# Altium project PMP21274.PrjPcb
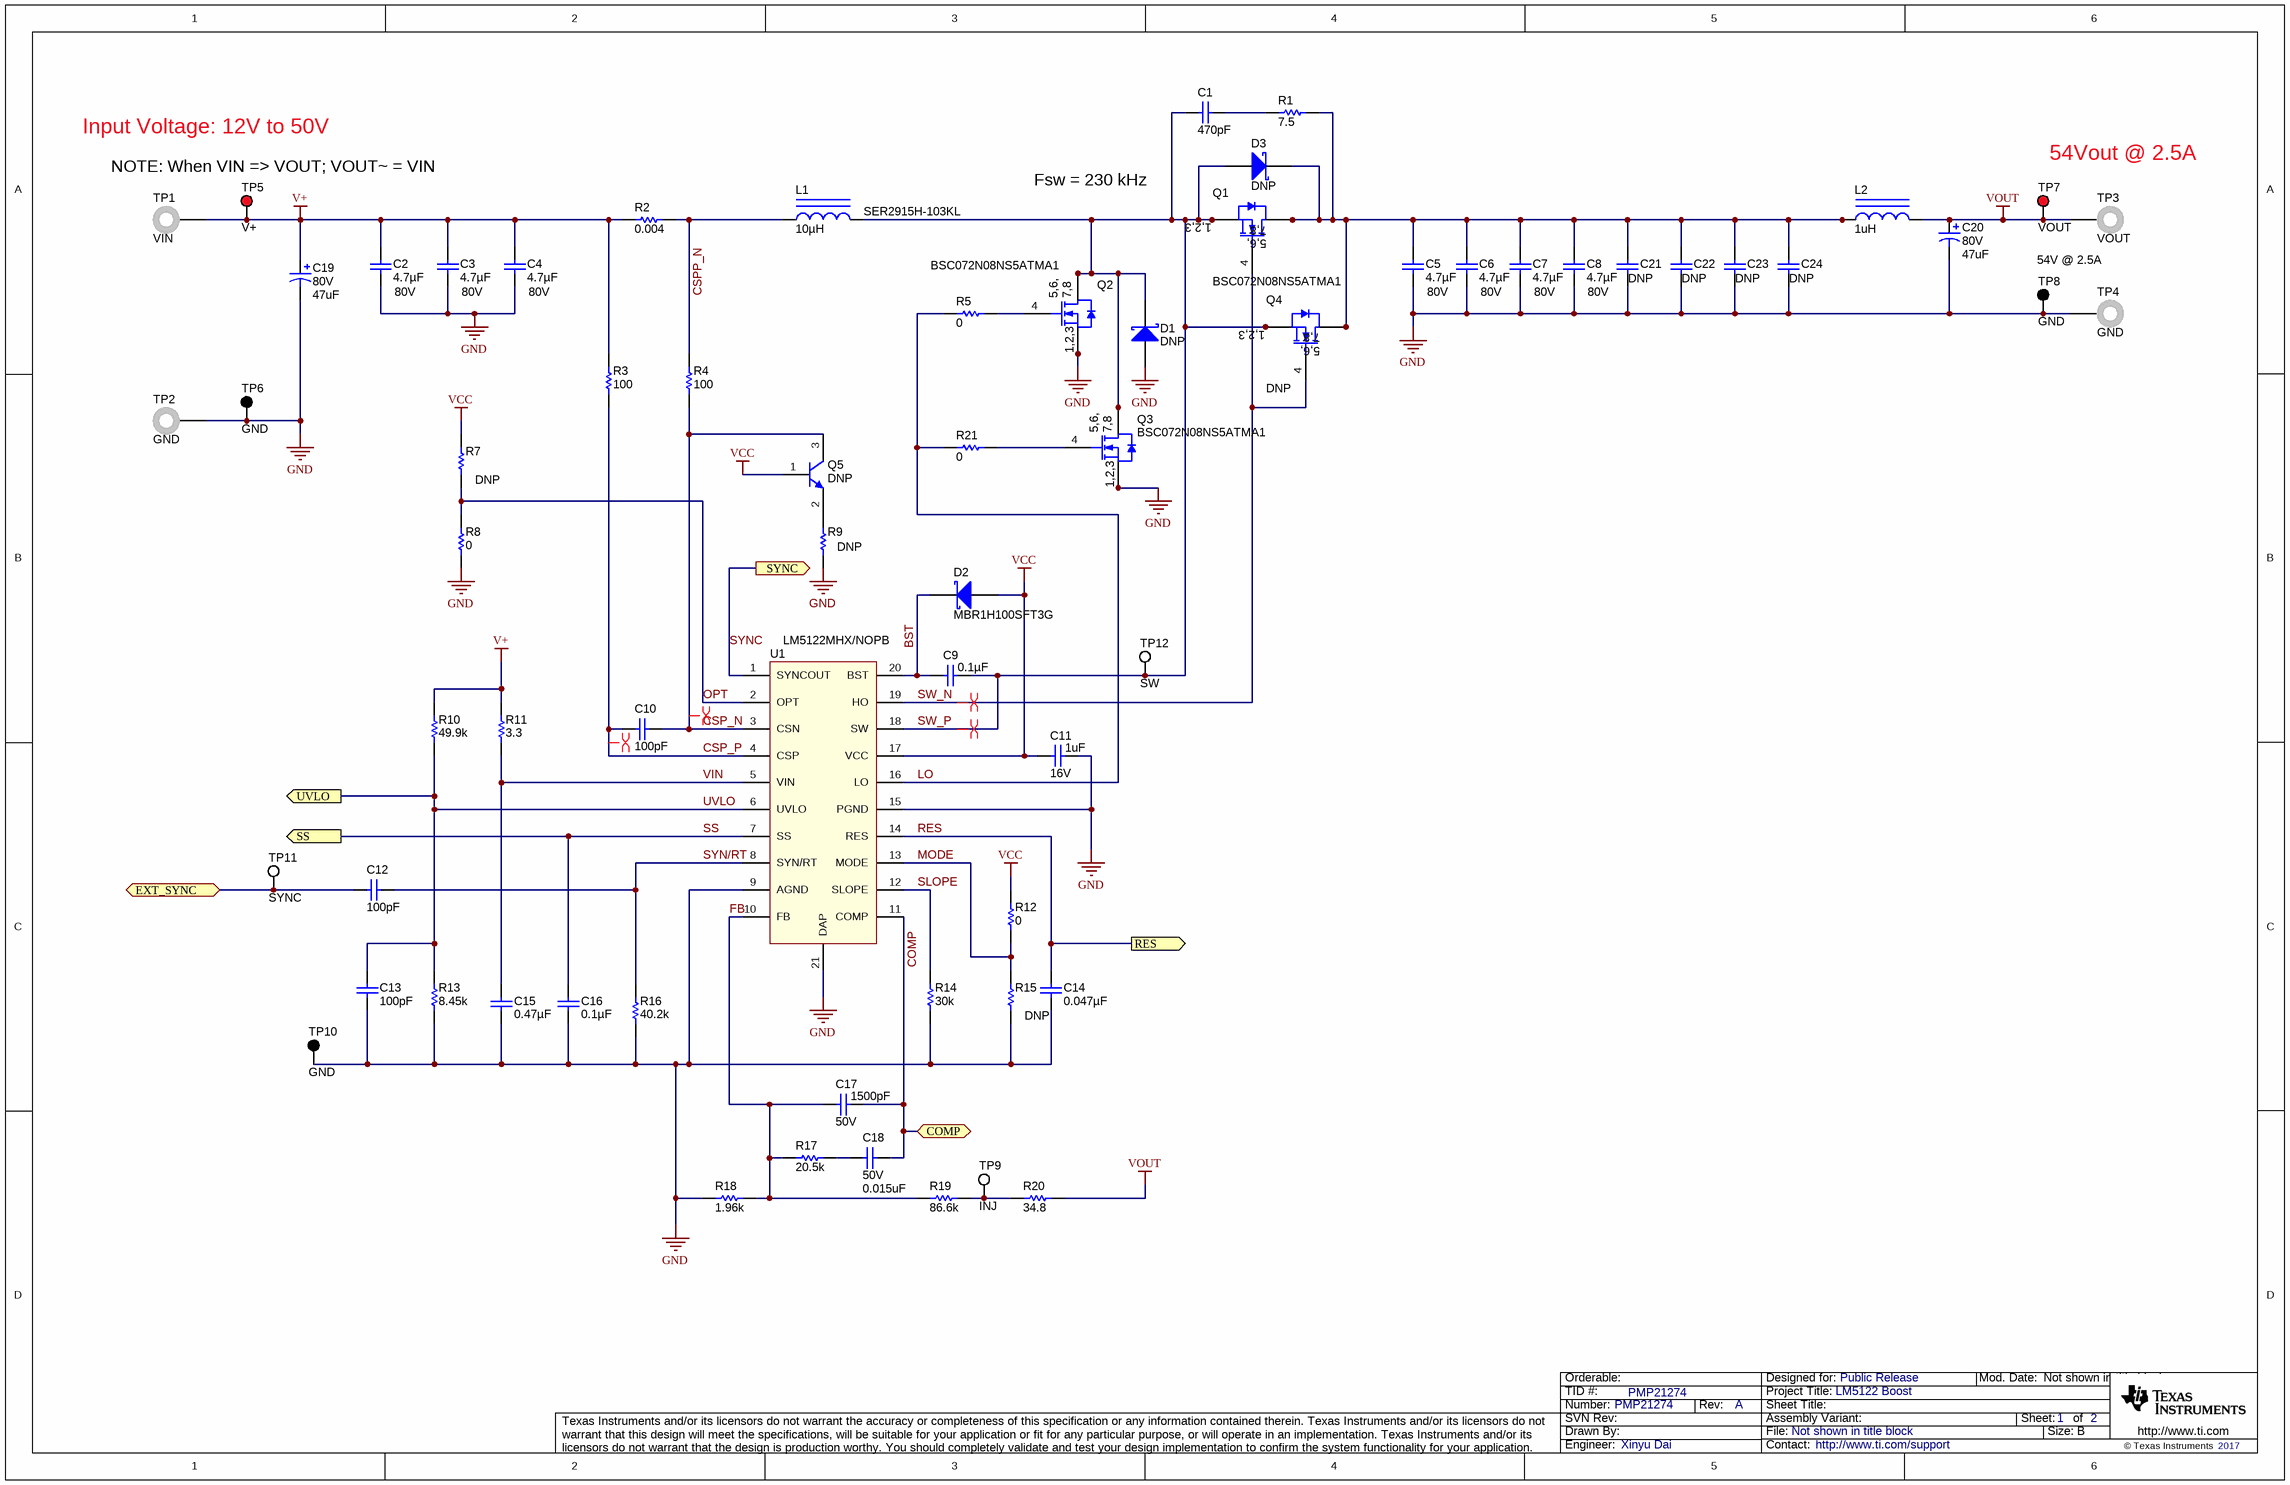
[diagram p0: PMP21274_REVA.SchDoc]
CopyrightYear: 2017; PCB_Layout: Xinyu Dai; PCB_Rev: A; PRJ_Customer: Public Release; PRJ_Engineer: Xinyu Dai; PRJ_Number: PMP21274; PRJ_Title: LM5122 Boost; SCH_Rev: A; TechSupport: http://www.ti.com/support; TID: PMP21274
2 sheets, 83 parts. Net scope: flat (ports and power ports of the same name join across sheets).
Board file: PMP21274_REVA.PcbDoc
Sheets:
  PMP21274_REVA.SchDoc
  PMP21274_REVA_Hardware.SchDoc

## Sheet PMP21274_REVA.SchDoc
size 431 x 279 mm; Date: Not shown in title block; ApprovedBy: Not shown in title block; CheckedBy: Not shown in title block; Author: Not shown in title block; CompanyName: Not shown in title block; Engineer: Not shown in title block; Organization: Not shown in title block; Address1: Not shown in title block; Address2: Not shown in title block; Address3: Not shown in title block; Address4: Not shown in title block; DocumentNumber: 1; Revision: Use project parameter SCH_Rev; SheetNumber: 1; SheetTotal: 2; PageSetup: Record=PageOptions¦CenterHorizontal=True¦CenterVertical=True¦PrintScale=1.00¦XCorrection=1.00¦YCorrection=1.00¦PrintKind=0¦BorderSize=5000000¦LeftOffset=0¦BottomOffset=0¦Orientation=2¦PaperLength=1000¦PaperWidth=1000¦Scale=100¦PaperSource=15¦PrintQuality=600¦MediaType=1¦DitherType=10¦PaperKind=Letter¦PrintScaleMode=1

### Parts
C1  ValueDisplayed: 470pF  [0805L]  (hidden comment: GRM2165C2A471JA01D)
C2  ValueDisplayed: 4.7µF  Value2: 80V  [1210L]  (hidden comment: GRM32ER71K475KE14L)
C3  ValueDisplayed: 4.7µF  Value2: 80V  [1210L]  (hidden comment: GRM32ER71K475KE14L)
C4  ValueDisplayed: 4.7µF  Value2: 80V  [1210L]  (hidden comment: GRM32ER71K475KE14L)
C5  ValueDisplayed: 4.7µF  Value2: 80V  [1210L]  (hidden comment: GRM32ER71K475KE14L)
C6  ValueDisplayed: 4.7µF  Value2: 80V  [1210L]  (hidden comment: GRM32ER71K475KE14L)
C7  ValueDisplayed: 4.7µF  Value2: 80V  [1210L]  (hidden comment: GRM32ER71K475KE14L)
C8  ValueDisplayed: 4.7µF  Value2: 80V  [1210L]  (hidden comment: GRM32ER71K475KE14L)
C9  ValueDisplayed: 0.1µF  [0603L]  (hidden comment: GRM188R71E104KA01D)
C10  ValueDisplayed: 100pF  [0603L]  (hidden comment: GRM1885C1H101JA01D)
C11  VDC_V: 16V  ValueDisplayed: 1uF  [0603L]  (hidden comment: GCM188R71C105KA64D)
C12  ValueDisplayed: 100pF  [0603L]  (hidden comment: GRM1885C1H101JA01D)
C13  ValueDisplayed: 100pF  [0603L]  (hidden comment: GRM1885C1H101JA01D)
C14  ValueDisplayed: 0.047µF  [0603L]  (hidden comment: GRM188R71E473KA01D)
C15  ValueDisplayed: 0.47µF  [0805L]  (hidden comment: GRM21BR72A474KA73L)
C16  ValueDisplayed: 0.1µF  [0603L]  (hidden comment: GRM188R71E104KA01D)
C17  VDC_V: 50V  ValueDisplayed: 1500pF  [0603L]  (hidden comment: GRM1885C1H152JA01D)
C18  VDC_V: 50V  ValueDisplayed: 0.015uF  [0603L]  (hidden comment: GRM188R71H153KA01D)
C19  VDC_V: 80V  ValueDisplayed: 47uF  [SM_RADIAL_G]  (hidden comment: EEE-FK1K470P)
C20  VDC_V: 80V  ValueDisplayed: 47uF  [SM_RADIAL_G]  (hidden comment: EEE-FK1K470P)
C21  DNP  [1210L]
C22  DNP  [1210L]
C23  DNP  [1210L]
C24  DNP  [1210L]
D1  DNP  [SMA]
D2  MBR1H100SFT3G  [SOD-123FL]
D3  DNP  [SMA]
L1  SER2915H-103KL  ValueDisplayed: 10µH  [SER2915H]
L2  ValueDisplayed: 1uH  [XAL4020]  (hidden comment: XAL4020-102MEB)
Q1  BSC072N08NS5ATMA1  [PG-TDSON-8]
Q2  BSC072N08NS5ATMA1  [PG-TDSON-8]
Q3  BSC072N08NS5ATMA1  [PG-TDSON-8]
Q4  DNP  [PG-TDSON-8]
Q5  DNP  [SOT-23L]
R1  ValueDisplayed: 7.5  [2010L]  (hidden comment: ERJ-12ZYJ7R5U)
R2  ValueDisplayed: 0.004  [2512L]  (hidden comment: ERJ-M1WSF4M0U)
R3  ValueDisplayed: 100  [0603L]  (hidden comment: ESR03EZPJ101)
R4  ValueDisplayed: 100  [0603L]  (hidden comment: ESR03EZPJ101)
R5  value 0  [0603L]  (hidden comment: ERJ-3GEY0R00V)
R7  DNP  [0603L]
R8  value 0  [0603L]  (hidden comment: ERJ-3GEY0R00V)
R9  DNP  [0603L]
R10  value 49.9k  [0603L]  (hidden comment: CRCW060349K9FKEA)
R11  value 3.3  [0603L]  (hidden comment: CRCW06033R30JNEA)
R12  value 0  [0603L]  (hidden comment: ERJ-3GEY0R00V)
R13  ValueDisplayed: 8.45k  [0603L]  (hidden comment: CRCW06038K45FKEA)
R14  ValueDisplayed: 30k  [0603L]  (hidden comment: CRCW060330K0JNEA)
R15  DNP  [0603L]
R16  value 40.2k  [0603L]  (hidden comment: CRCW060340K2FKEA)
R17  ValueDisplayed: 20.5k  [0603L]  (hidden comment: CRCW060320K5FKEA)
R18  value 1.96k  [0603L]  (hidden comment: CRCW06031K96FKEA)
R19  ValueDisplayed: 86.6k  [0603L]  (hidden comment: CRCW060386K6FKEA)
R20  ValueDisplayed: 34.8  [0603L]  (hidden comment: CRCW060334R8FKEA)
R21  value 0  [0603L]  (hidden comment: ERJ-3GEY0R00V)
TP1  VIN  [Keystone575-8]
TP2  GND  [Keystone575-8]
TP3  VOUT  [Keystone575-8]
TP4  GND  [Keystone575-8]
TP5  V+  [Keystone5010]
TP6  GND  [Keystone5011]
TP7  VOUT  [Keystone5010]
TP8  GND  [Keystone5011]
TP9  INJ  [Keystone5002]
TP10  GND  [Keystone5011]
TP11  SYNC  [Keystone5002]
TP12  SW  [Keystone5002]
U1  LM5122MHX/NOPB  [MXA20A_L]

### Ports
COMP, EXT_SYNC, RES, SS, SYNC (out), UVLO

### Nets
GND: C2.2 C3.2 C4.2 C5.2 C6.2 C7.2 C8.2 C11.1 C13.2 C14.2 C15.2 C16.2 C19.2(-) C20.2(-) C21.2 C22.2 C23.2 C24.2 D1.2(A) Q2.1(S) Q2.2(S) Q2.3(S) Q3.1(S) Q3.2(S) Q3.3(S) R8.1 R9.1 R13.1 R14.1 R15.1 R16.1 R18.1 TP2.1 TP4.1 TP6.1 TP8.1 TP10.1 U1.9(AGND) U1.15(PGND) U1.21(DAP)
V+: C2.1 C3.1 C4.1 C19.1(+) R2.1 R3.2 R10.2 R11.2 TP1.1 TP5.1
VCC: C11.2 D2.2(A) Q5.1(B) R7.2 R12.2 U1.17(VCC)
VOUT: C20.1(+) L2.2 R20.2 TP3.1 TP7.1
BST: C9.2 D2.1(K) U1.20(BST)
COMP: C17.1 C18.1 U1.11(COMP) ; port COMP
CSP_N: C10.1 Q5.3(C) R4.1 U1.3(CSN)
CSP_P: C10.2 R3.1 U1.4(CSP)
CSPP_N: L1.1 R2.2 R4.2
EXT_SYNC: C12.2 TP11.1 ; port EXT_SYNC
FB: C17.2 R17.1 R18.2 R19.1 U1.10(FB)
LO: R5.2 R21.2 U1.16(LO)
MODE: R12.1 R15.2 U1.13(MODE)
OPT: R7.1 R8.2 U1.2(OPT)
RES: C14.1 U1.14(RES) ; port RES
SLOPE: R14.2 U1.12(SLOPE)
SS: C16.1 U1.7(SS) ; port SS
SW_N: Q1.4(G) Q4.4(G) U1.19(HO)
SW_P: C1.2 C9.1 D1.1(K) D3.2(A) L1.2 Q1.1(S) Q1.2(S) Q1.3(S) Q2.5(D) Q2.6(D) Q2.7(D) Q2.8(D) Q2.9(D) Q3.5(D) Q3.6(D) Q3.7(D) Q3.8(D) Q3.9(D) Q4.1(S) Q4.2(S) Q4.3(S) TP12.1 U1.18(SW)
SYN/RT: C12.1 R16.2 U1.8(SYN/RT)
SYNC: U1.1(SYNCOUT) ; port SYNC
UVLO: C13.1 R10.1 R13.2 U1.6(UVLO) ; port UVLO
VIN: C15.1 R11.1 U1.5(VIN)
NetC1_1: C1.1 R1.1
NetC5_1: C5.1 C6.1 C7.1 C8.1 C21.1 C22.1 C23.1 C24.1 D3.1(K) L2.1 Q1.5(D) Q1.6(D) Q1.7(D) Q1.8(D) Q1.9(D) Q4.5(D) Q4.6(D) Q4.7(D) Q4.8(D) Q4.9(D) R1.2
NetC18_2: C18.2 R17.2
NetQ2_4: Q2.4(G) R5.1
NetQ3_4: Q3.4(G) R21.1
NetQ5_2: Q5.2(E) R9.2
NetR19_2: R19.2 R20.1 TP9.1

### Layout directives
differential pair: CSP_N, CSP_P, SW_N, SW_P

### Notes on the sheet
- Input Voltage: 12V to 50V
- NOTE: When VIN => VOUT; VOUT~ = VIN
- 54Vout @ 2.5A
- Fsw = 230 kHz
- 54V @ 2.5A

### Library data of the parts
C1 = GRM2165C2A471JA01D: CAP, CERM, 470pF, 100V, +/-5%, C0G/NP0, 0805; Manufacturer: MuRata; Polarized: N; CompType: Capacitor; U/M: EA; Cap_F: 0.00000000047; Tolerance_%: 5; VDC_V: 100; TaMin_C: -55; TaMax_C: 125; Cap_Case: 0805
C2-C8 = GRM32ER71K475KE14L: CAP, CERM, 4.7 µF, 80 V, +/- 10%, X7R, 1210; Manufacturer: MuRata; Polarized: N; CompType: Capacitor; Value: 4.7uF; U/M: EA; Cap_F: 0.0000047; Tolerance_%: 10; Value1: Unknown; VDC_V: 80; TaMin_C: -55; TaMax_C: 125; Cap_Case: 1210; SizeArea_mm2: 8; SizeAreaWB_mm2: 14.7; SizeX_mm: 3.2; SizeY_mm: 2.5; SizeZ_mm: 2.7; AEC Category: Q200
C9 = GRM188R71E104KA01D: CAP, CERM, 0.1 µF, 25 V,+/- 10%, X7R, 0603; Manufacturer: MuRata; Polarized: N; CompType: Capacitor; Value: 0.1uF; U/M: EA; Cap_F: 0.0000001; Tolerance_%: 10; VDC_V: 25; Value2: 25V; TaMin_C: -55; TaMax_C: 125; Cap_Case: 0603; SizeArea_mm2: 1.28; SizeAreaWB_mm2: 4.68; SizeX_mm: 1.6; SizeY_mm: 0.8; SizeZ_mm: 1; AEC Category: Q200; Green_Lifecycle: Active; Green_REACh: Passed
C10 C12 C13 = GRM1885C1H101JA01D: CAP, CERM, 100pF, 50V, +/-5%, C0G/NP0, 0603; Manufacturer: MuRata; Polarized: N; CompType: Capacitor; U/M: EA; Cap_F: 0.0000000001; Tolerance_%: 5; VDC_V: 50; TaMin_C: -55; TaMax_C: 125; Cap_Case: 0603
C11 = CMP-0007136-5: CAP, CERM, 1 uF, 16 V, +/- 10%, X7R, AEC-Q200 Grade 1, 0603; Manufacturer: MuRata; TaMin_C: -55°C; Polarized: N; SizeAreaWB_mm2: 4.68; Value1: Unknown; U/M: EA; Value: 1uF; TaMax_C: 125°C; SizeZ_mm: 1; SizeX_mm: 1.6; SizeY_mm: 0.8; Cap_Case: 0603; SizeArea_mm2: 1.28; CompType: Capacitor; AEC Qualified: Y; Cap_F: 1µF; AEC Category: Q200
C14 = GRM188R71E473KA01D: CAP, CERM, 0.047uF, 25V, +/-10%, X7R, 0603; Manufacturer: MuRata; Polarized: N; CompType: Capacitor; U/M: EA; Cap_F: 0.000000047; Tolerance_%: 10; VDC_V: 25; TaMin_C: -55; TaMax_C: 125; Cap_Case: 0603
C15 = GRM21BR72A474KA73L: CAP, CERM, 0.47uF, 100V, +/-10%, X7R, 0805; Manufacturer: MuRata; Polarized: N; CompType: Capacitor; U/M: EA; Cap_F: 0.00000047; Tolerance_%: 10; VDC_V: 100; TaMin_C: -55; TaMax_C: 125; Cap_Case: 0805
C16 = GRM188R71E104KA01D: CAP, CERM, 0.1uF, 25V, +/-10%, X7R, 0603; Manufacturer: MuRata; Polarized: N; CompType: Capacitor; U/M: EA; Cap_F: 0.0000001; Tolerance_%: 10; VDC_V: 25; TaMin_C: -55; TaMax_C: 125; Cap_Case: 0603
C17 = CMP-0007186-4: CAP, CERM, 1500 pF, 50 V, +/- 5%, C0G/NP0, 0603; Manufacturer: MuRata; TaMin_C: -55°C; Polarized: N; SizeAreaWB_mm2: 4.68; Value1: Unknown; U/M: EA; Value: 1500pF; TaMax_C: 125°C; SizeZ_mm: 1; SizeX_mm: 1.6; SizeY_mm: 0.8; Cap_Case: 0603; SizeArea_mm2: 1.28; CompType: Capacitor; Cap_F: 1.5nF; AEC Category: Q200
C18 = CMP-0007438-4: CAP, CERM, 0.015 uF, 50 V, +/- 10%, X7R, 0603; Manufacturer: MuRata; TaMin_C: -55°C; Polarized: N; SizeAreaWB_mm2: 4.68; Value1: Unknown; U/M: EA; TaMax_C: 125°C; SizeZ_mm: 1; SizeX_mm: 1.6; SizeY_mm: 0.8; Cap_Case: 0603; SizeArea_mm2: 1.28; CompType: Capacitor; Cap_F: 15nF; AEC Category: Q200
C19 C20 = CMP-0011200-2: CAP, AL, 47 uF, 80 V, +/- 20%, 0.7 ohm, AEC-Q200 Grade 2, SMD; Manufacturer: Panasonic; TaMin_C: -55°C; ESR_ohm: 7d; Polarized: Y; SizeAreaWB_mm2: 172.2; Value1: 0.7 ohm; U/M: EA; Value: 47uF; TaMax_C: 105°C; SizeZ_mm: 10.2; SizeX_mm: 12; SizeY_mm: 10.3; Cap_Case: G; SizeArea_mm2: 123.6; CompType: Capacitor; Cap_F: 47µF; IRMS_A: 2dA; AEC Grade: 2; AEC Category: Q200
C21-C24 = GRM32ER71K475KE14L: CAP, CERM, 4.7 µF, 80 V, +/- 10%, X7R, 1210; Manufacturer: MuRata; Polarized: N; CompType: Capacitor; Value: 4.7uF; ValueDisplayed: 4.7µF; U/M: EA; Cap_F: 0.0000047; Tolerance_%: 10; Value1: Unknown; VDC_V: 80; Value2: 80V; TaMin_C: -55; TaMax_C: 125; Cap_Case: 1210; SizeArea_mm2: 8; SizeAreaWB_mm2: 14.7; SizeX_mm: 3.2; SizeY_mm: 2.5; SizeZ_mm: 2.7; AEC Category: Q200
D1 D3 = CMP-0028811-1: Diode, Schottky, 100 V, 2 A, AEC-Q101, SMA; Manufacturer: Fairchild Semiconductor; PartNumber: SSA210; Io_A: 2A; Green_Lifecycle: Not Set; SizeAreaWB_mm2: 37.3428; Vr_V: 100V; Green_REACh: Incomplete; TJmax_C: 175°C; U/M: EA; Value: 100V; SizeZ_mm: 2.87; SizeX_mm: 5.59; SizeY_mm: 2.92; Vf_V: 8dV; Value2: 0.8V; SizeArea_mm2: 16.3228; AEC Qualified: Y; AEC Category: Q101
D2 = CMP-0028625-1: Diode, Schottky, 100 V, 1 A, SOD-123FL; Manufacturer: ON Semiconductor; Io_A: 1A; Green_Lifecycle: Active; SizeAreaWB_mm2: 12.19; Vr_V: 100V; Green_REACh: Passed; TJmax_C: 175°C; U/M: EA; Value: 100V; SizeZ_mm: 0.98; SizeX_mm: 3.6; SizeY_mm: 1.65; Vf_V: 7.6dV; Value2: 0.76V; SizeArea_mm2: 5.94; AEC Category: Q101; RJC_CperW: 85
L1 = SER2915H-103KL: Inductor, Shielded E Core, Ferrite, 10 µH, 23.4 A, 0.00186 ohm, SMD; Manufacturer: Coilcraft; Value: 10uH; Ind_H: 10.0E-6; Imax_A: 23.4; Irms: 30A @ 40C rise; Isat: 23.4A @ 30% inductance drop; Value2: 23.4A; SizeAreaWB_mm2: 651.82; SizeArea_mm2: 552.42; SizeX_mm: 27.9; SizeY_mm: 19.8; SizeZ_mm: 15.36; AEC Category: Q200; Green_Lifecycle: Not Set; Green_REACh: Incomplete
L2 = CMP-0060983-1: Inductor, Shielded, Composite, 1 uH, 8.75 A, 0.01 ohm, SMD; Manufacturer: Coilcraft; Isat: 8.75A @ 30% inductance drop; Irms: 9.6A @ 40C rise; Green_Lifecycle: Not Set; SizeAreaWB_mm2: 28.09; DCR_ohm: 0.01; Green_REACh: Incomplete; Value: 1uH; Imax_A: 8.75A; SizeZ_mm: 2.1; SizeX_mm: 4.3; SizeArea_mm2: 18.49; Ind_H: 1µH; AEC Category: Q200
Q1-Q3 = CMP-0000905-1: MOSFET, N-CH, 80 V, 74 A, PG-TDSON-8; Alternate Manufacturer: None; Manufacturer: Infineon Technologies; SizeZ_mm: 1.12; ChType: N; Value2: 24 nC; VdsMax_V: 80V; SizeX_mm: 5.99; SizeY_mm: 4.9; Vgs_V: 20V; QgTyp_nC: 24; Value: 80V; SizeArea_mm2: 29.351; AEC Category: Q101; IdsMax_A: 74A; SizeAreaWB_mm2: 55.131; U/M: EA
Q4 = CMP-0000905-1: MOSFET, N-CH, 80 V, 74 A, PG-TDSON-8; PartNumber: BSC072N08NS5ATMA1; Alternate Manufacturer: None; Manufacturer: Infineon Technologies; SizeZ_mm: 1.12; ChType: N; Value2: 24 nC; VdsMax_V: 80V; SizeX_mm: 5.99; SizeY_mm: 4.9; Vgs_V: 20V; QgTyp_nC: 24; Value: 80V; SizeArea_mm2: 29.351; AEC Category: Q101; IdsMax_A: 74A; SizeAreaWB_mm2: 55.131; U/M: EA
Q5 = CMP-0000416-2: Transistor, NPN, 80 V, 0.5 A, SOT-23; PartNumber: MMBTA06-7-F; Manufacturer: Diodes Inc.; TaMax_C: 150°C; Value1: 0.5 A; Vcesat1_V: 2.5dV; SizeX_mm: 2.5; SizeY_mm: 3; TaMin_C: -55°C; IcRated_A: 5dA; CompType: BJT; SizeZ_mm: 1.1; Value: 80 V; SizeArea_mm2: 7.5; NPN: 1; Vceo_V: 80V; PNP: 0; AEC Category: Q101; SizeAreaWB_mm2: 14; U/M: EA
R1 = CMP-0016199-2: RES, 7.5, 5%, 0.75 W, AEC-Q200 Grade 0, 2010; Manufacturer: Panasonic; Power_W: 750mW; TempCo: 600 ppm/C; Value_Code: 7R50; U/M: EA; Value: 7.5; EIA_Code: E24; SizeX_mm: 5; SizeY_mm: 2.5; SizeZ_mm: 1.66; Value2: 0.75W; SizeArea_mm2: 12.5; CompType: Resistor; AEC Qualified: Y; AEC Grade: 0; AEC Category: Q200
R2 = CMP-0015813-2: RES, 0.004, 1%, 1 W, 2512; Manufacturer: Panasonic; Power_W: 1W; TempCo: 350 ppm/C; Value_Code: 4L000; U/M: EA; Value: 0.004; Res_ohm: 4m; SizeX_mm: 6.3; SizeY_mm: 3.2; SizeZ_mm: 0.71; SizeArea_mm2: 20.16; CompType: Resistor; AEC Category: Q200
R3 R4 = CMP-0025882-3: RES, 100, 5%, 0.25 W, AEC-Q200 Grade 0, 0603; Manufacturer: Rohm; Power_W: 250mW; TempCo: 200 ppm/C; Value_Code: 100R; U/M: EA; Value: 100; EIA_Code: E24; SizeX_mm: 1.6; SizeY_mm: 0.8; SizeZ_mm: 1; Value2: 0.25W; SizeArea_mm2: 1.28; AEC Qualified: Y; VDC_V: 150V; AEC Grade: 0; AEC Category: Q200; CompType: Resistor
R5 R8 R12 R21 = ERJ-3GEY0R00V: RES, 0 ohm, 5%, 0.1W, 0603; Manufacturer: Panasonic; CompType: Resistor; Value_Code: 0000; Tolerance_%: 5; Power_W: 0.1; VDC_V: 50; TempCo: 600 ppm/C; EIA_Code: E24; U/M: EA
R7 R15 = ERJ-3GEY0R00V: RES, 0 ohm, 5%, 0.1W, 0603; Manufacturer: Panasonic; CompType: Resistor; Value: 0; Value_Code: 0000; Tolerance_%: 5; Power_W: 0.1; VDC_V: 50; TempCo: 600 ppm/C; EIA_Code: E24; U/M: EA
R9 = CMP-0022532-3: RES, 60.4 k, 1%, 0.1 W, 0603; Manufacturer: Vishay-Dale; PartNumber: CRCW060360K4FKEA; Power_W: 100mW; TempCo: 100 ppm/C; Value_Code: 60k4; U/M: EA; Value: 60.4k; EIA_Code: E96; SizeX_mm: 1.6; SizeY_mm: 0.8; SizeZ_mm: 1; Value2: 0.1W; SizeArea_mm2: 1.28; CompType: Resistor; VDC_V: 75V; AEC Category: Q200
R10 = CRCW060349K9FKEA: RES, 49.9k ohm, 1%, 0.1W, 0603; Manufacturer: Vishay-Dale; CompType: Resistor; Res_ohm: 49900; Value_Code: 49k9; Tolerance_%: 1; Power_W: 0.1; VDC_V: 75; TempCo: 100 ppm/C; EIA_Code: E96; U/M: EA
R11 = CRCW06033R30JNEA: RES, 3.3 ohm, 5%, 0.1W, 0603; Manufacturer: Vishay-Dale; CompType: Resistor; Value_Code: 3R30; Tolerance_%: 5; Power_W: 0.1; VDC_V: 75; TempCo: 200 ppm/C; EIA_Code: E24; U/M: EA
R13 = CRCW06038K45FKEA: RES, 8.45 k, 1%, 0.1 W, 0603; Manufacturer: Vishay-Dale; CompType: Resistor; Value: 8.45k; Res_ohm: 8450; Value_Code: 8k45; Tolerance_%: 1; Power_W: 0.1; Value2: 0.1W; VDC_V: 75; TempCo: 100 ppm/C; EIA_Code: E96; U/M: EA; SizeArea_mm2: 1.28; SizeX_mm: 1.6; SizeY_mm: 0.8; AEC Category: Q200
R14 = CRCW060330K0JNEA: RES, 30 k, 5%, 0.1 W, 0603; Manufacturer: Vishay-Dale; CompType: Resistor; Value: 30k; Res_ohm: 30000; Value_Code: 30k0; Tolerance_%: 5; Power_W: 0.1; Value2: 0.1W; VDC_V: 75; TempCo: 200 ppm/C; SizeArea_mm2: 1.28; SizeX_mm: 1.6; SizeY_mm: 0.8; SizeZ_mm: 1; EIA_Code: E24; U/M: EA; AEC Category: Q200; Green_Lifecycle: Active; Green_REACh: Passed
R16 = CRCW060340K2FKEA: RES, 40.2k ohm, 1%, 0.1W, 0603; Manufacturer: Vishay-Dale; CompType: Resistor; Res_ohm: 40200; Value_Code: 40k2; Tolerance_%: 1; Power_W: 0.1; VDC_V: 75; TempCo: 100 ppm/C; EIA_Code: E96; U/M: EA
R17 = CRCW060320K5FKEA: RES, 20.5 k, 1%, 0.1 W, 0603; Manufacturer: Vishay-Dale; CompType: Resistor; Value: 20.5k; Res_ohm: 20500; Value_Code: 20k5; Tolerance_%: 1; Power_W: 0.1; Value2: 0.1W; VDC_V: 75; TempCo: 100 ppm/C; EIA_Code: E96; U/M: EA; SizeArea_mm2: 1.28; SizeX_mm: 1.6; SizeY_mm: 0.8; AEC Category: Q200; Green_Lifecycle: Active; Green_REACh: Passed
R18 = CRCW06031K96FKEA: RES, 1.96k ohm, 1%, 0.1W, 0603; Manufacturer: Vishay-Dale; CompType: Resistor; Res_ohm: 1960; Value_Code: 1k96; Tolerance_%: 1; Power_W: 0.1; VDC_V: 75; TempCo: 100 ppm/C; EIA_Code: E96; U/M: EA
R19 = CRCW060386K6FKEA: RES, 86.6 k, 1%, 0.1 W, 0603; Manufacturer: Vishay-Dale; CompType: Resistor; Value: 86.6k; Res_ohm: 86600; Value_Code: 86k6; Tolerance_%: 1; Power_W: 0.1; Value2: 0.1W; VDC_V: 75; TempCo: 100 ppm/C; EIA_Code: E96; U/M: EA; SizeArea_mm2: 1.28; SizeX_mm: 1.6; SizeY_mm: 0.8; AEC Category: Q200; Green_Lifecycle: Active; Green_REACh: Passed
R20 = CRCW060334R8FKEA: RES, 34.8, 1%, 0.1 W, 0603; Manufacturer: Vishay-Dale; CompType: Resistor; Value: 34.8; Value_Code: 34R8; Tolerance_%: 1; Power_W: 0.1; Value2: 0.1W; VDC_V: 75; TempCo: 100 ppm/C; SizeArea_mm2: 1.28; SizeX_mm: 1.6; SizeY_mm: 0.8; EIA_Code: E96; U/M: EA; AEC Category: Q200
TP1-TP4 = 575-8: Standard Banana Jack, Uninsulated, 8.9mm; Manufacturer: Keystone; CompType: Connector; Green_Lifecycle: Active; Green_REACh: Passed
TP5 TP7 = CMP-0055147-1: Test Point, Multipurpose, Red, TH; Manufacturer: Keystone; PartNumber: 5010; CNHeader: FALSE; Green_Lifecycle: Active; Green_REACh: Passed; ContactFinish: Silver; CT: TRUE
TP6 TP8 TP10 = CMP-0055148-1: Test Point, Multipurpose, Black, TH; Manufacturer: Keystone; PartNumber: 5011; CNHeader: FALSE; Green_Lifecycle: Active; Green_REACh: Passed; ContactFinish: Silver; CT: TRUE
TP9 TP11 TP12 = CMP-0055139-1: Test Point, Miniature, White, TH; Manufacturer: Keystone; PartNumber: 5002; CNHeader: FALSE; Green_Lifecycle: Active; Green_REACh: Passed; ContactFinish: Silver; CT: TRUE
U1 = LM5122MHX/NOPB: Wide Input Synchronous Boost Controller with Multiple Phase Capability, PWP0020A; Manufacturer: Texas Instruments; Alternate PartNumber: LM5122MHE/NOPB; SymbolCreator: a0411947; CompType: IC; U/M: EA

## Sheet PMP21274_REVA_Hardware.SchDoc
size 431 x 279 mm; Date: Not shown in title block; ApprovedBy: Not shown in title block; CheckedBy: Not shown in title block; Author: Not shown in title block; CompanyName: Not shown in title block; Engineer: Not shown in title block; Organization: Not shown in title block; Address1: Not shown in title block; Address2: Not shown in title block; Address3: Not shown in title block; Address4: Not shown in title block; DocumentNumber: 2; Revision: Use project parameter SCH_Rev; SheetNumber: 2; SheetTotal: 2; PageSetup: Record=PageOptions¦CenterHorizontal=True¦CenterVertical=True¦PrintScale=1.00¦XCorrection=1.00¦YCorrection=1.00¦PrintKind=0¦BorderSize=5000000¦LeftOffset=0¦BottomOffset=0¦Orientation=2¦PaperLength=1000¦PaperWidth=1000¦Scale=100¦PaperSource=15¦PrintQuality=600¦MediaType=1¦DitherType=10¦PaperKind=Letter¦PrintScaleMode=1
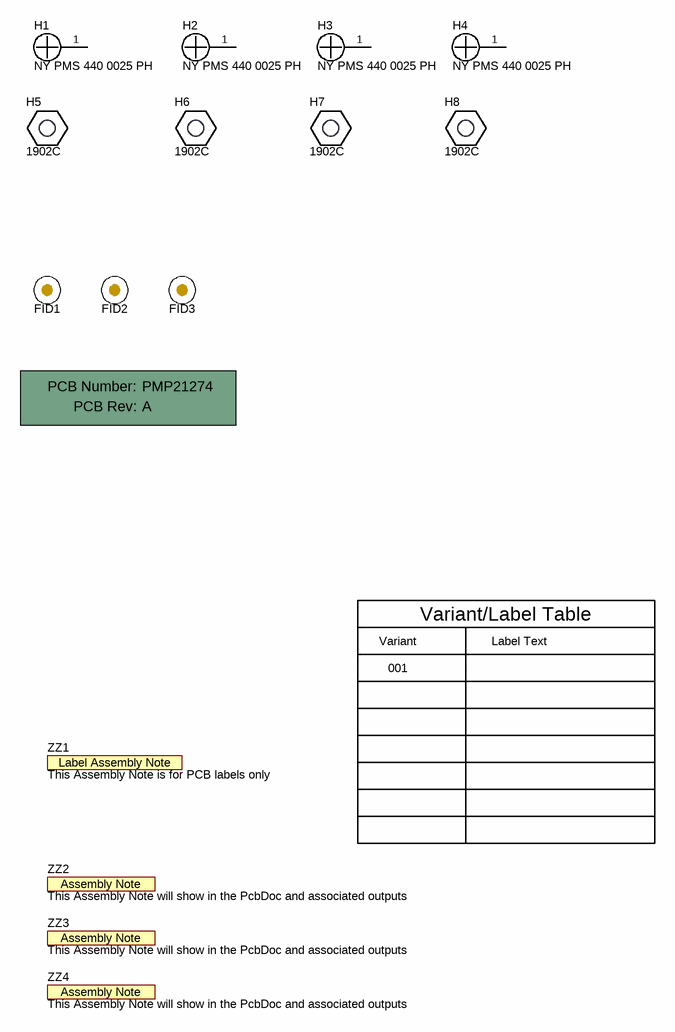
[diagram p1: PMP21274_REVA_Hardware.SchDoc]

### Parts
!PCB  Printed Circuit Board  (value not drawn)  (mechanical)
FID1  Fiducial  [Fiducial10-20]  (value not drawn)
FID2  Fiducial  [Fiducial10-20]  (value not drawn)
FID3  Fiducial  [Fiducial10-20]  (value not drawn)
H1  NY PMS 440 0025 PH  [NY PMS 440 0025 PH]
H2  NY PMS 440 0025 PH  [NY PMS 440 0025 PH]
H3  NY PMS 440 0025 PH  [NY PMS 440 0025 PH]
H4  NY PMS 440 0025 PH  [NY PMS 440 0025 PH]
H5  1902C  [Keystone_1902C]
H6  1902C  [Keystone_1902C]
H7  1902C  [Keystone_1902C]
H8  1902C  [Keystone_1902C]
ZZ1  This Assembly Note is for PCB labels only  [AssemblyNoteLabel]  (no BOM)
ZZ2  This Assembly Note will show in the PcbDoc and associated outputs  [AssemblyNote]  (no BOM)
ZZ3  This Assembly Note will show in the PcbDoc and associated outputs  [AssemblyNote]  (no BOM)
ZZ4  This Assembly Note will show in the PcbDoc and associated outputs  [AssemblyNote]  (no BOM)

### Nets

Not connected (* = marked no-connect by the designer): H1 1; H2 1; H3 1; H4 1

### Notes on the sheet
- Variant
- Variant/Label Table
- Label Text
- 001

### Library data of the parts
!PCB = PCB: Manufacturer: Any; PartNumber: PMP21274; SymbolCreator: a0412235
FID1-FID3 = Fiducial: Fiducial mark.  There is nothing to buy or mount.; SymbolCreator: codlsc
H1-H4 = NY PMS 440 0025 PH: Machine Screw, Round, #4-40 x 1/4, Nylon, Philips panhead; Manufacturer: B&F Fastener Supply; CompType: Hardware; SymbolCreator: codlsc; U/M: EA; Green_Lifecycle: Not Set; Green_REACh: Incomplete
H5-H8 = 1902C: Standoff, Hex, 0.5"L #4-40 Nylon; Manufacturer: Keystone; Green_Lifecycle: Active; Green_REACh: Passed; SymbolCreator: a0412235
ZZ1 = AssemblyNoteLabel: SymbolCreator: a0412235
ZZ2-ZZ4 = AssemblyNote: SymbolCreator: codlsc

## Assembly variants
001: not fitted C21 C22 C23 C24 D1 D3 FID1 FID2 FID3 Q4 Q5 R7 R9 R15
